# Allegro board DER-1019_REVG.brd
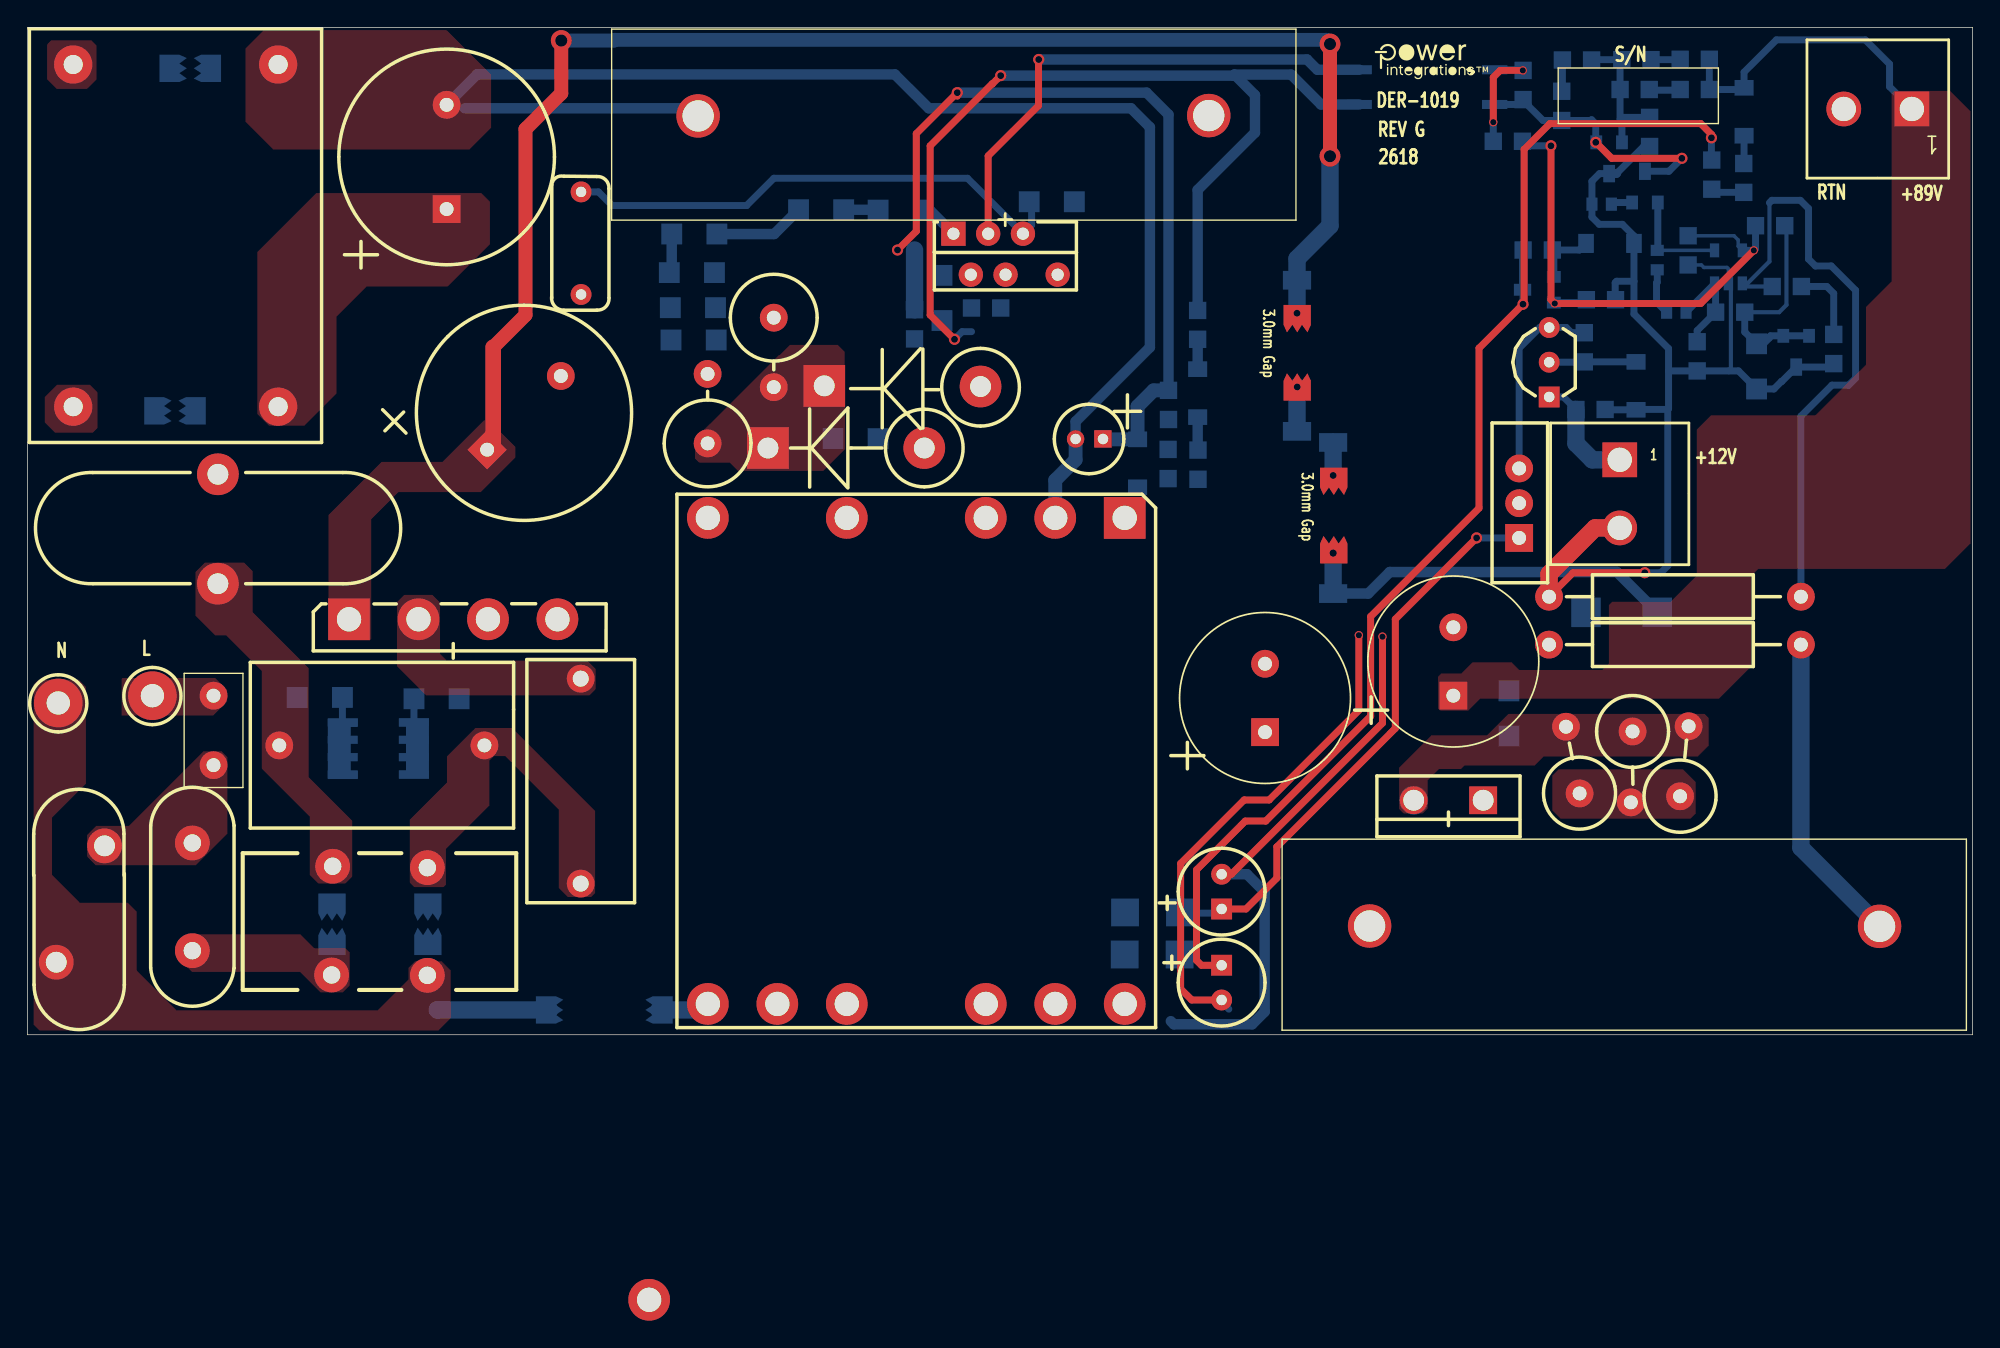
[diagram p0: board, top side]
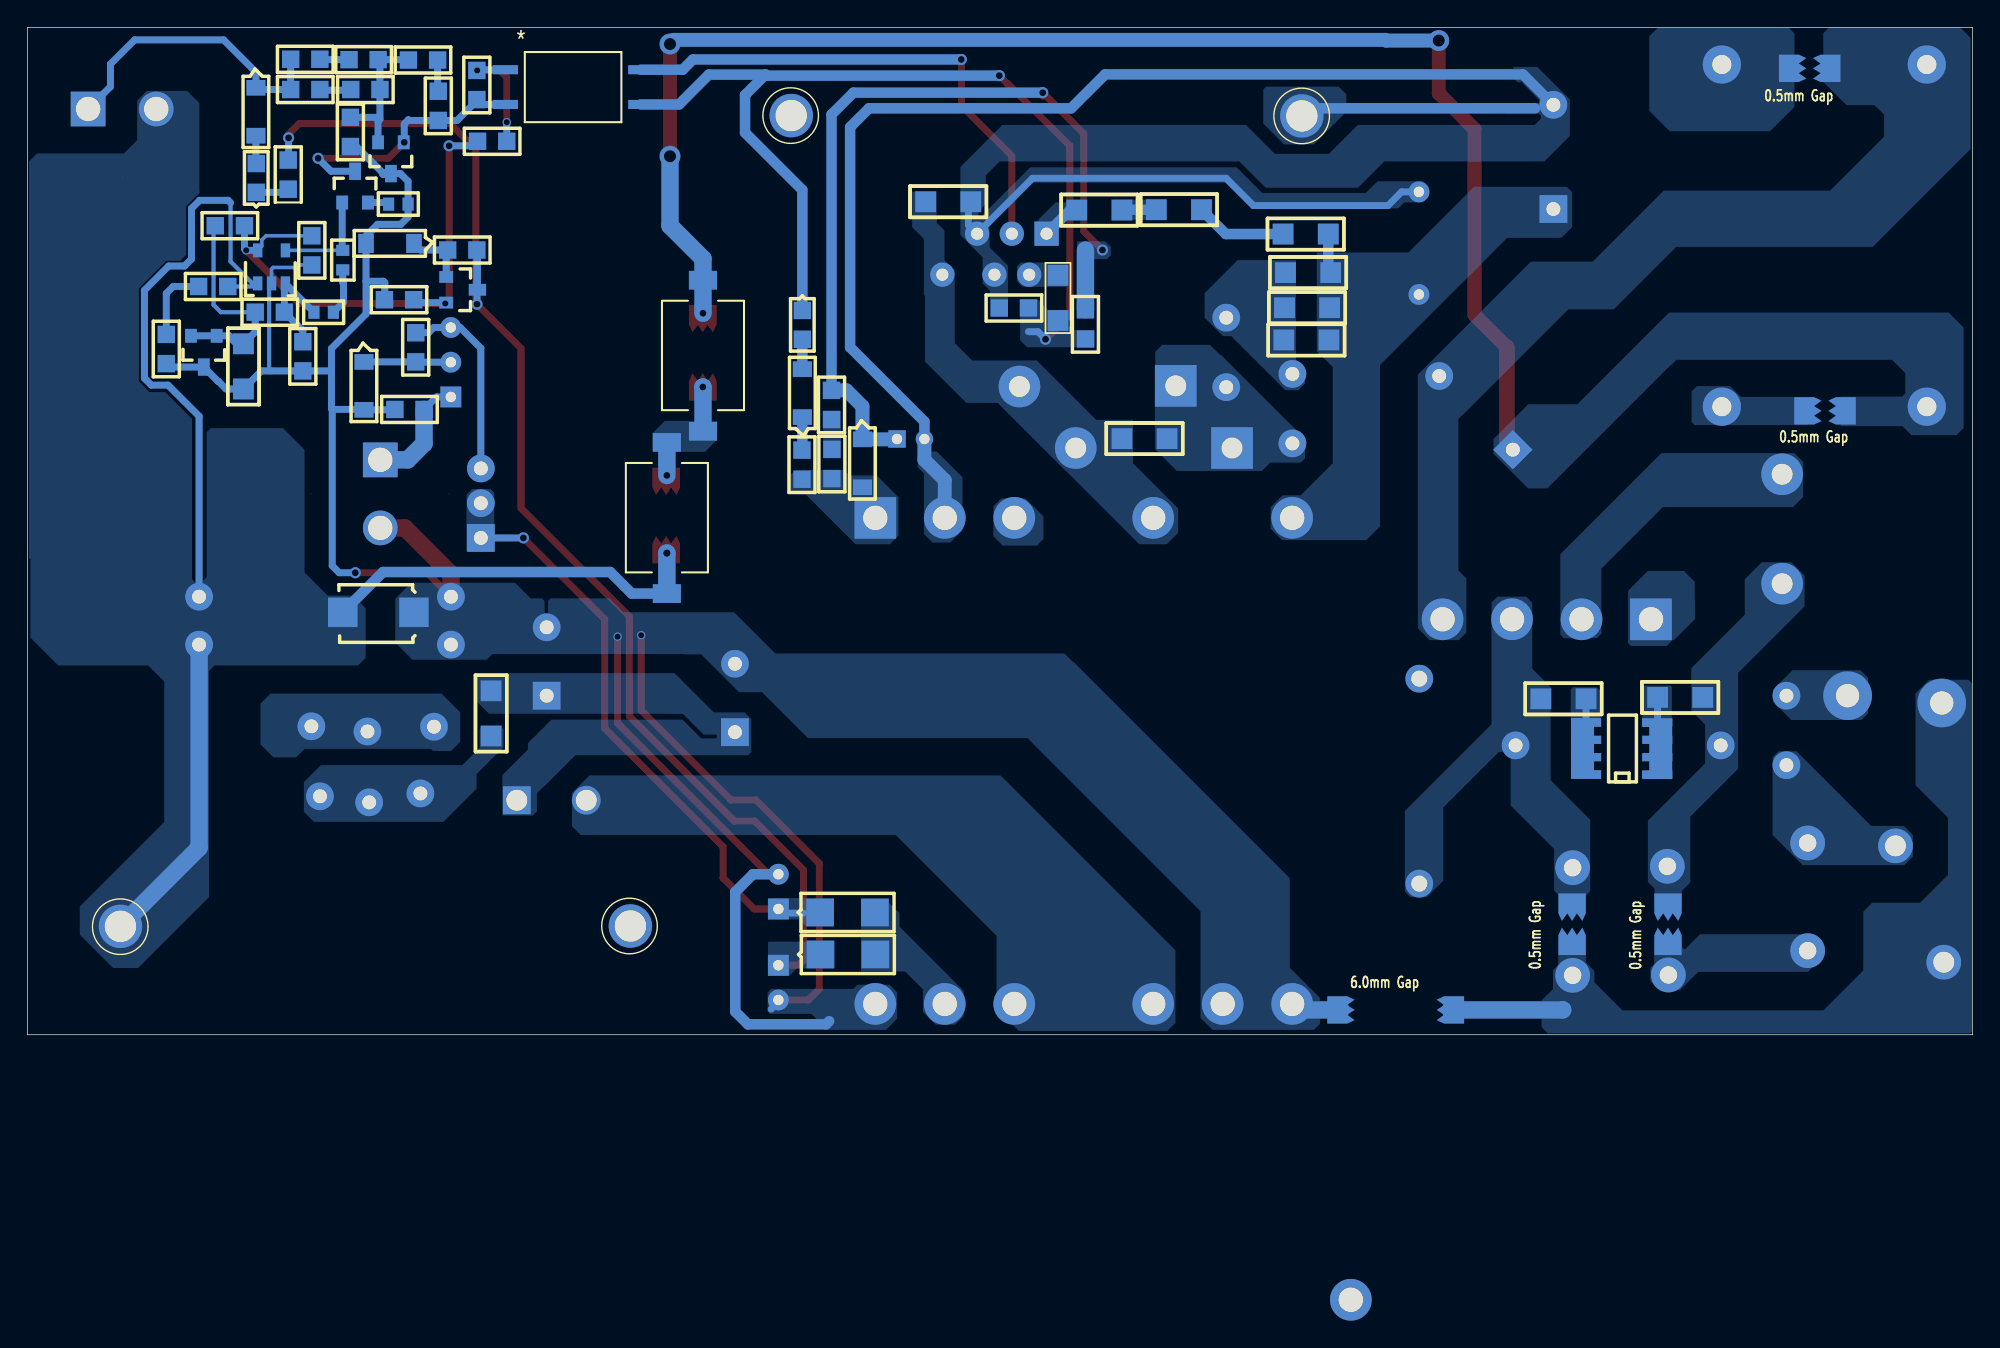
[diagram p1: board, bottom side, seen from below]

Outline 142.24 x 73.66 mm; copper layers: TOP, BOTTOM. Coordinates in mm from the lower left corner of the outline.
Outline path: 0,73.66 142.24,73.66 142.24,0 0,0 0,73.66

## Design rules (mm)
constraint set DEFAULT: min track width 0.508

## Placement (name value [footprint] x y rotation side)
BR1  GBU10KL-BP  [PIDAXBRIDGEGBU8]  23.52 30.38 0 top
C1  100 uF  [PIPOLCAPCYLD250LS100030]  87.33 9.19 90 top
C2  120 uF  [PIPOLCAPCLYD630LS300040]  33.62 42.78 45 top
C3  120 uF  [PIPOLCAPCLYD630LS300040]  30.66 60.38 90 top
C4  100 pF  [PISMC1206]  73.25 60.91 0 bottom
C5  4.7 uF  [PISMC0805]  69.04 53.14 0 bottom
C6  10 nF  [PISMC1206]  47.07 50.8 0 bottom
C7  47 pF  [PISMC1206]  58.9 43.59 0 bottom
C8  330 pF  [PISMC0805]  83.41 40.67 90 bottom
C9  22 uF  [PIPOLCAPCLYD5MMD030]  77.65 43.56 180 top
C10  100 nF  [PISMC1206]  126.44 50.52 270 bottom
C11  470 pF  [PISMC1206]  108.33 21.84 90 bottom
C12  47 uF  [PIPOLCAPCYLD250LS100030]  87.33 5.08 270 top
C13  100 nF  [PISMC0805]  113.23 45.72 0 bottom
C14  10 nF  [PISMC0805]  129.72 54.71 180 bottom
C16  220 uF  [PIPOLCAPCLYD500LS200040]  90.5 22.12 90 top
C18  220 uF  [PIPOLCAPCLYD500LS200040]  104.27 24.79 90 top
C19  100 nF  [PISMC0805]  112.19 66.85 90 bottom
C21  68 nF  [PISMC0805]  118.59 69.11 180 bottom
C33  680 nF  [PINPXCAPRAD710X430720040]  33.42 21.16 180 top
C34  220 nF  [PISMC0603]  121.28 52.83 180 bottom
C40  100 nF  [PISMC0805]  121.44 56.29 90 bottom
C41  100 nF  [PISMC0805]  114 53.75 0 bottom
C45  330 nF  [PINPXCAPRAD710X315590046]  40.46 26.04 270 top
C46  68 nF  [PI_NP_CAP_RAD9P8X4P2X7P5X0P6]  40.49 54.13 90 top
CY1  2.2 nF  [PISMC8X6MM]  92.84 55.17 270 bottom
CY2  2.2 nF  [PISMC8X6MM]  95.48 43.31 270 bottom
D1  1N5408G  [PIDV300X200X060DO15D0201AD]  62.08 47.4 0 top
D2  S1MLHRVG  [PI_SM_SOD-123_12]  81.18 43.54 270 bottom
D3  US1D  [PISMDSMA]  84.25 5.87 180 bottom
D4  STTH12R06D  [PIDVT0220ACREVA]  106.45 17.14 180 top
D7  S1AB-13-F  [PISMSMB]  113.97 30.89 0 bottom
D10  1N4148WS  [PISMDSOD323]  85.57 52.96 270 bottom
D11  US1D  [PISMDSMA]  84.28 8.94 180 bottom
D13  1N4148WS  [PISMDSOD323]  125.5 61.59 90 bottom
D14  1N5408G  [PIDV300X200X060DO15D0201AD#2]  54.15 42.9 0 top
F1  10 A  [PI_MST_MICROFUSE]  13.61 22.25 270 top
J2  FAN  [PI_HDR_2PIN_PHOENIX_196LS]  116.43 42.04 270 top
J4  FAN  [PI_HDR_2PIN_PHOENIX_196LS]  137.79 67.69 180 top
L1  100 uH  [PI2P455X1062LS315D60]  13.93 32.98 90 top
L2  1.1 mH  [PI_IND_4P_10X20MMD050]  22.15 3.28 90 top
L3  10 mH  [PIIND4P1180X827LS985590D055]  3.35 70.94 0 top
L4  48 Ohms  [PISMFERRITEBEAD1206]  66.88 55.52 270 bottom
MTG_HOLE1  No 2  [PIMTGHOLE2]  98.15 7.95 0 top
MTG_HOLE2  No 2  [PIMTGHOLE2]  135.43 7.92 0 top
MTG_HOLE3  No 2  [PIMTGHOLE2]  49.05 67.18 0 top
MTG_HOLE4  No 2  [PIMTGHOLE2]  86.39 67.21 0 top
NOREF  -  []  0 0 90 top
NOREF#2  -  []  -150.78 54.23 0 top
NOREF#3  -  []  0 73.66 0 top
NOREF#4  -  []  -228.6 -144.78 0 top
NOREF#5  -  []  141.78 0.33 90 top
NOREF#6  -  []  97.97 72.34 0 top
NOREF#7  -  []  91.74 0.33 0 top
Q1  ZTX692B  [PITO92R100]  111.28 46.63 90 top
Q2  MMBTA06LT1  [PISMSOT23123_1]  110.52 54.48 270 bottom
Q3  MMBTA06LT1  [PISMSOT23123_1]  118.29 61.95 180 bottom
R1  100 k  [PISMR1206]  19.74 24.66 0 bottom
R2  100 k  [PISMR1206]  28.27 24.56 0 bottom
R5  2 M  [PISMR1206]  47.12 58.55 0 bottom
R6  3.30 M  [PISMR1206]  56.39 60.33 0 bottom
R7  2.7 M  [PISMR1206]  62.2 60.3 0 bottom
R8  20  [PI_3W_VRES220LS200D040]  54.58 52.43 270 top
R9  20  [PI_3W_VRES220LS200D040]  49.74 43.24 90 top
R10  200 k  [PISMR1206]  50.24 55.73 180 bottom
R12  2.74 k  [PISMR0805]  64.87 50.88 90 bottom
R13  200 k  [PISMR1206]  47.02 53.16 0 bottom
R14  100  [PISMR0805]  83.44 44.98 90 bottom
R15  4.22 k  [PISMR0805]  126.36 59.16 0 bottom
R16  75  [PI2WRESD200LS725D040]  117.37 22.17 270 top
R17  75  [PI2WRESD200LS725D040#2]  113.5 17.64 101.5 top
R18  3.30 k  [PISMR0805]  113.84 49.2 90 bottom
R19  53.6 k  [PISMR0805]  125.58 52.83 180 bottom
R20  1 k  [PISMR0805]  132.08 49.07 90 bottom
R21  3.9 k  [PISMR0805]  122.1 50.67 270 bottom
R23  13.3 k  [PISMR0805]  111.51 57.38 180 bottom
R24  100  [PISMR0603]  114.4 60.73 0 bottom
R25  1.00 k  [PISMR0805]  109.37 70.51 270 bottom
R26  825 R  [PISMR0805]  109.32 65.33 180 bottom
R27  0.080  [PI1WRESD200LS725D040]  111.27 32.03 0 top
R28  15 k  [PISMR0805]  112.24 71.27 0 bottom
R29  340 k  [PISMR0805]  122.99 71.32 180 bottom
R30  10 k  [PISMR0805]  118.62 67.08 270 bottom
R32  10 k  [PISMR0805]  122.99 69.11 180 bottom
R40  47.0  [PISMR0805]  85.6 40.61 90 bottom
R41  3.32 k  [PISMR0603]  119.18 55.93 90 bottom
R50  0.080  [PI1WRESD200LS725D040]  111.27 28.52 0 top
R52  100  [PISMR0805]  123.16 61.82 90 bottom
R55  7.50 k  [PISMR0805]  118.72 71.3 180 bottom
R57  75  [PI2WRESD200LS725D040]  120.85 17.43 83.6 top
RT1  1  [PI_RAD_240X630LS310D050]  12.06 6.15 90 top
RV1  275 Vac  [PIDISC675X225LS335X140040]  2.11 5.3 90 top
SG1  0.5mm gap  [PI_SPARK_GAP_0P5MM]  22.28 8.08 90 bottom
SG2  0.5mm gap  [PI_SPARK_GAP_0P5MM]  29.29 8.08 90 bottom
SG3  0.5mm gap  [PI_SPARK_GAP_0P5MM]  11.91 70.66 180 bottom
SG4  0.5mm gap  [PI_SPARK_GAP_0P5MM]  10.79 45.62 180 bottom
SG7  3.0mm gap  [PI_SPARK_GAP_3P0MM]  95.52 37.97 270 top
SG8  3.0mm gap  [PI_SPARK_GAP_3P0MM]  92.85 49.86 270 top
SG9  6.0mm gap  [PI_SPARK_GAP_6P0MM]  42.19 1.81 0 bottom
SW1  SPDT SLIDE  [PI_SWITCH_SPDT_SLIDE_PCBM_1]  109.08 36.33 0 top
T1  PQ35/35  [PI_BOBBIN_PQ35_35V_12P]  65 20.02 270 top
TP1  WHT  [PITPKEYSTONE125X125]  2.26 24.26 0 top
TP2  BLK  [PITPKEYSTONE125X125]  9.14 24.79 0 top
U1  CAP300DG  [PI_IC_SMD_SO8_CAPZERO]  23.06 19.02 90 bottom
U2  TOP7078E  [PIICESIP76TH]  67.72 58.57 0 top
U3  SFH6106-3T  [SMD-4_VO_VIS]  102.34 69.29 180 bottom
U4  LM321MF/NOPB  [PISMSOT235]  125.4 54.94 180 bottom
U5  LM431BIM3/NOPB  [PISMSOT23123]  116.6 65.25 0 bottom
U6  LM431BIM3/NOPB  [PISMSOT23123]  130.28 51.1 0 bottom
VR4  MMSZ5241B-7-F  [PI_SM_SOD-123_12]  113.97 57.86 0 bottom
VR6  MMSZ5240B-7-F  [PI_SM_SOD-123_12]  85.57 45.16 90 bottom
VR7  MMSZ4700T1G  [PI_SM_SOD-123_12]  117.63 49.2 270 bottom
VR8  MMSZ5267BT1G  [PI_SM_SOD-123_12]  125.53 69.24 270 bottom

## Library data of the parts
BR1 = DISCRETE BRIDGE_+~~-: room: 1
C1 C12 = CAP POL: alternate symbols: (pipolcapcyld250ls100030h); room: 2
C2 C3 = CAP POL: alternate symbols: (pipolcapclyd630ls3000401260h); room: 1
C4 C6 C7 = CAP NP: tolerance: 10; room: 1
C5 = CAP NP: alternate symbols: (Unisem_RMCF0805UL); room: 1
C8 = CAP NP: alternate symbols: (Unisem_RMCF0805UL); tolerance: 10; room: 1
C9 = CAP POL: alternate symbols: (pipolcapclyd5x11mmd030H); tolerance: 20; room: 1
C10 C14 = CAP NP: room: 3
C11 = CAP NP: tolerance: 10; room: 2
C13 C19 C21 C40 C41 = CAP NP: alternate symbols: (Unisem_RMCF0805UL); room: 3
C16 C18 = CAP POL: alternate symbols: (pipolcapclyd500ls2000401200lh); room: 2
C33 = CAP NP: alternate symbols: (pinpxcaprad710x430720040_h); room: 1
C34 = CAP NP: alternate symbols: (Unisem_RMCF0603UL); room: 3
C45 = CAP NP: alternate symbols: (pinpxcaprad710x315590046H)
C46 = CAP NP
CY1 CY2 = CAP NP: tolerance: 20; room: 1
D1 D14 = DIODE: alternate symbols: (pidv300x472x060do14wbead,pidax800x225060do15do201ad,pidv300x200x060do14wbead); room: 1
D2 D10 D13 = DIODE: room: 1
D3 D7 D11 = DIODE: room: 2
D4 = DIODE
F1 = FUSE: alternate symbols: (pi_MST_microfuseH)
J2 J4 = CON2: alternate symbols: (pi_hdr_2pin_phoenix_196lsobl); room: 3
L1 = INDUCTOR: room: 1
L2 = TORRID 4P_14_23
L3 = INDUCTOR_4P-12P
L4 = INDUCTOR_BEAD
MTG_HOLE1-MTG_HOLE4 = MTG_HOLE_2-56
Q1 = NPN_EBC: alternate symbols: (PIT092100)
Q2 = NPN_BEC: room: 2
Q3 = NPN_BEC: room: 3
R1 R2 R5-R7 R10 R13 = R: room: 1
R8 R9 = R: alternate symbols: (pi_3w_vres220ls300d040,pi_3w_vres220ls400d040,pi_3w_vres220ls500d040,pi_3w_hres220ls800d040); room: 1
R12 R14 R40 = R: alternate symbols: (Unisem_RMCF0805UL); room: 1
R15 R18 R19 R21 R28-R30 R32 R55 = R: alternate symbols: (Unisem_RMCF0805UL); room: 3
R16 R17 R57 = R: alternate symbols: (pi2wresd200ls900d040,pi2wvresd200ls300d040,pi2wvresd200ls400d040); room: 2
R20 = R: room: 3
R23 R25 R26 R52 = R: alternate symbols: (Unisem_RMCF0805UL); room: 2
R24 R41 = R: alternate symbols: (Unisem_RMCF0603UL); room: 3
R27 R50 = R: alternate symbols: (pi1wvresd200ls300d040); room: 2
RT1 = THERMISTOR
RV1 = VARISTOR: room: 1
SG1-SG4 SG7 SG8 = SPARK_GAP: room: 1
SG9 = SPARK_GAP
SW1 = SW SLIDE-SPDT
T1 = BPQ35/35_12P/GENERIC: room: 1
TP1 TP2 = TESTPOINT: alternate symbols: (TP_5010-14)
U1 = CAPZero: room: 1
U2 = TOPSwitch-GaN_eSIP7
U3 = OPTO_A_B_AKCE: User Part Number: PN; Tolerance: TOL
U4 = LM321_SOT23-5
U5 U6 = TL431/SOT-23_CAR: room: 3
VR4 VR6-VR8 = DIODE_ZENER: room: 2

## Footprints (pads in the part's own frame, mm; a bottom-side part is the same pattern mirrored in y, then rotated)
PI1WRESD200LS725D040
  round 2.032 hole 1.016: 1(0,0) 2(18.415,0)
PI2P455X1062LS315D60
  round 3.048 hole 1.524: 1(0,0) 2(8.001,0)
PI2WRESD200LS725D040
  round 2.032 hole 1.016: 1(0,0) 2(5.156,-0.051)
PI2WRESD200LS725D040#2
  round 2.032 hole 1.016: 1(0,0) 2(4.978,0)
PI_3W_VRES220LS200D040
  round 2.032 hole 1.016: 1(0,0) 2(5.08,0)
PI_BOBBIN_PQ35_35V_12P
  rect 3.048x3.048 hole 1.778: 1(-17.77,15.24)
  round 3.048 hole 1.778: 2(-17.77,10.16) 3(-17.77,5.08) 4(-17.77,-5.08) 5(39.406,-19.533) 6(-17.77,-15.24) 7(17.77,-15.24) 8(17.77,-10.16) 9(17.77,-5.08) 10(17.77,5.08) 11(17.77,10.16) 12(17.77,15.24)
PI_HDR_2PIN_PHOENIX_196LS
  rect 2.54x2.54 hole 1.778: 1(0,0)
  round 2.54 hole 1.778: 2(4.978,0)
PI_IC_SMD_SO8_CAPZERO
  rect 0.599x2.2 smd: 1(0,0) 2(1.27,0) 3(2.54,0) 4(3.81,0) 5(3.81,5.199) 6(2.54,5.199) 7(1.27,5.199) 8(0,5.199)
PI_IND_4P_10X20MMD050
  round 2.54 hole 1.27: 1(1.092,-0.099) 2(1.067,-7.099) 3(8.938,-7.099) 4(9.04,-0.175)
PI_MST_MICROFUSE
  round 2.032 hole 1.016: 1(-2.54,0) 2(2.54,0)
PI_NP_CAP_RAD9P8X4P2X7P5X0P6
  round 1.524 hole 0.762: 1(0,0) 2(7.501,0)
PI_RAD_240X630LS310D050
  round 2.54 hole 1.27: 1(0,0) 2(7.874,0)
PI_SM_SOD-123_12
  rect 1.143x1.397 smd: 1(0,0) 2(3.505,0)
PI_SPARK_GAP_0P5MM
  custom 0.5x0.5 smd: 1(-1.25,0) 2(1.25,0)
PI_SPARK_GAP_3P0MM
  custom 0.5x0.5 smd: 1(-2.499,0) 2(2.499,0)
PI_SPARK_GAP_6P0MM
  custom 0.5x0.5 smd: 1(-4,0) 2(4,0)
PI_SWITCH_SPDT_SLIDE_PCBM_1
  rect 2.032x2.032 hole 1.016: 1(0,0)
  round 2.032 hole 1.016: 2(0,2.54) 3(0,5.08)
PIDAXBRIDGEGBU8
  rect 3.048x3.048 hole 1.778: 1(0,0)
  round 3.048 hole 1.778: 2(5.08,0) 3(10.16,0) 4(15.24,0)
PIDISC675X225LS335X140040
  round 2.54 hole 1.524: 1(0,0) 2(8.509,-3.531)
PIDV300X200X060DO15D0201AD
  rect 3.048x3.048 hole 1.524: 1(-3.81,0.051)
  round 3.048 hole 1.524: 2(7.62,0)
PIDV300X200X060DO15D0201AD#2
  rect 3.048x3.048 hole 1.524: 1(0,0)
  round 3.048 hole 1.524: 2(11.43,0)
PIDVT0220ACREVA
  rect 2.032x2.032 hole 1.524: 1(0,0)
  round 2.032 hole 1.524: 2(5.08,0)
PIICESIP76TH
  rect 1.778x1.778 hole 0.889: 1(0,0)
  round 1.778 hole 0.889: 2(1.27,-2.997) 3(2.54,0) 4(3.81,-2.997) 5(5.08,0) 7(7.62,-2.997)
PIIND4P1180X827LS985590D055
  round 2.794 hole 1.397: 1(0,0) 6(0,-25.019) 7(14.986,-25.019) 12(14.986,0)
PIMTGHOLE2
  round 3.175 hole 2.286: 1(0,0)
PINPXCAPRAD710X315590046
  round 2.032 hole 1.168: 1(0,0) 2(14.986,0)
PINPXCAPRAD710X430720040
  round 2.032 hole 1.016: 1(0,0) 2(15.001,0)
PIPOLCAPCLYD5MMD030
  rect 1.27x1.27 hole 0.762: 1(-1.001,0)
  round 1.27 hole 0.762: 2(1.001,0)
PIPOLCAPCLYD500LS200040
  rect 2.032x2.032 hole 1.016: 1(0,0)
  round 2.032 hole 1.016: 2(5.001,0)
PIPOLCAPCLYD630LS300040
  rect 2.032x2.032 hole 1.016: 1(0,0)
  round 2.032 hole 1.016: 2(7.62,0)
PIPOLCAPCYLD250LS100030
  rect 1.524x1.524 hole 0.762: 1(0,0)
  round 1.524 hole 0.762: 2(2.54,0)
PISMC8X6MM
  rect 1.369x2.06 smd: 1(0,0) 2(11.049,0)
PISMC0603
  rect 0.813x0.965 smd: 1(0,0) 2(1.422,0)
PISMC0805
  rect 1.27x1.27 smd: 1(0,0) 2(2.134,0)
PISMC1206
  rect 1.524x1.524 smd: 1(0,0) 2(3.302,0)
PISMDSMA
  rect 2.032x2.032 smd: 1(0,0) 2(4.013,0)
PISMDSOD323
  rect 1.27x1.27 smd: 1(0,0) 2(2.108,0)
PISMFERRITEBEAD1206
  rect 1.524x1.524 smd: 1(0,0) 2(3.302,0)
PISMR0603
  rect 0.813x0.965 smd: 1(0,0) 2(1.422,0)
PISMR0805
  rect 1.27x1.27 smd: 1(0,0) 2(2.134,0)
PISMR1206
  rect 1.524x1.524 smd: 1(0,0) 2(3.302,0)
PISMSMB
  rect 2.159x2.159 smd: 1(0,0) 2(5.207,0)
PISMSOT235
  rect 0.686x1.016 smd: 1(0,0) 2(1.016,0) 3(2.032,0) 4(2.032,2.413) 5(0,2.413)
PISMSOT23123
  rect 0.864x1.016 smd: 1(-1.88,0) 3(0,0)
  rect 0.864x1.27 smd: 2(-0.94,2.286)
PISMSOT23123_1
  rect 0.864x1.016 smd: 1(-0.93,-1.1) 2(0.95,-1.1)
  rect 0.864x1.27 smd: 3(0.01,1.186)
PITO92R100
  rect 1.524x1.524 hole 0.762: 1(0,0)
  round 1.524 hole 0.762: 2(2.54,0) 3(5.08,0)
PITPKEYSTONE125X125
  round 3.556 hole 1.702: 1(0,0)
SMD-4_VO_VIS
  rect 1.854x0.66 smd: 1(-4.953,1.27) 2(-4.953,-1.27) 3(4.953,-1.27) 4(4.953,1.27)

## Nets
SGND: C1.2 C10.2 C12.2 C13.2 C16.2 C18.2 C40.1 C41.2 D7.1 J2.2 R20.1 R21.2 R24.1 R27.1 R30.2 R50.1 SG9.2 T1.7 T1.8 T1.12 U4.2(V-) U5.2 U6.2 VR4.2 VR7.2
ISENSE: C14.2 CY2.2 D7.2 J4.2 MTG_HOLE2.1 R27.2 R50.2 SG7.2 U4.1
SOURCE: C3.2 C4.1 C5.2 C9.2 C46.2 L3.12 MTG_HOLE3.1 SG3.1 T1.2 U2.4 U2.5
VOUT: C11.2 C16.1 C18.1 D4.1 J4.1 R29.1 R32.1 VR8.1
N1180656: C3.1 C6.1 C46.1 L3.7 R5.1 R10.2 R13.1 SG4.1 T1.6
N1180866: BR1.1 C2.1 CY1.1 L3.6 SG4.2 SG8.1
N1181140: BR1.4 C2.2 L3.1 SG3.2
N1181144: R5.2 R6.1
N1181148: C4.2 C7.2 D1.2 D14.2 T1.4 U2.7
N1181266: C9.1 D2.1 R12.2 R14.2
N11509809: L2.2 RV1.1 SG2.1 SG9.1 TP1.1
N11618494: C8.1 D2.2 R40.1 T1.1
N11648004: R6.2 R7.1
N12700328: R7.2 U2.1
N12700744: C5.1 D10.1 L4.2 R12.1 U3.3
N12706416: C11.1 R16.2 R17.1 R57.1
N12706737: D4.2 R16.1 R17.2 R57.2 T1.9 T1.10
N12714802: C12.1 D3.1 Q2.3 R23.2 R52.2
N12714836: C40.2 C41.1 Q2.2(EMITTER) R15.1 R26.1 U4.5
N12714870: Q2.1 R23.1 VR4.1
N12715244: R25.1 R26.2 U3.1
N12715260: C21.1 R32.2
N12715348: C19.1 Q3.3 R25.2 U3.2 U5.1
N12715352: R29.2 R55.1
N12715398: C21.2 R28.2 R30.1 R55.2 U5.3(VREF)
N12715470: C19.2 R28.1
N12715572: C14.1 R20.2
N12715722: C10.1 R15.2 R19.1 U6.1 U6.3(VREF)
N12715816: C34.1 R19.2 R21.1 U4.3
N12715884: Q3.2(EMITTER) R24.2
N12720334: D3.2 D11.2 T1.11
N12771158: U2.3 U3.4(E)
N12827596: F1.1 TP2.1
N12850742: C6.2 R8.1 R9.2 R10.1 R13.2
N12884562: BR1.2 C45.1 L1.2
N12884633: BR1.3(AC2) C33.1 C45.2 L2.3 R2.2 SG2.2
N12888086: Q1.3 R18.2 SW1.3
N12888112: C13.1 J2.1 Q1.1(EMITTER)
N12888140: Q1.2 R18.1 VR7.1
N12889668: CY1.2 CY2.1 SG7.1 SG8.2
N12891407: L4.1 U2.2
N12908406: F1.2 RT1.2 RV1.2
N12908860: C33.2 L1.1 L2.4 R1.1 SG1.2
N12919791: C7.1 D1.1 D14.1 R8.2 R9.1
N12926277: R1.2 U1.1 U1.2 U1.3 U1.4
N12926285: R2.1 U1.5 U1.6 U1.7 U1.8(NC8)
N12928762: L2.1 RT1.1 SG1.1
N12942914: C1.1 D11.1 SW1.1 SW1.2
N12947787: D10.2 VR6.2
N12947838: R40.2 VR6.1
N12951060: C34.2 R41.1
N12953138: Q3.1 R41.2 U4.4
N13029746: C8.2 R14.1
N13057790: D13.1 R52.1
N13059217: D13.2 VR8.2

Pads without a net: MTG_HOLE1 1; MTG_HOLE4 1; T1 3 5

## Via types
v1: diameter 0.813, hole 0.508, TOP to BOTTOM, 17 vias
v2: diameter 0.61, hole 0.457, TOP to BOTTOM, 6 vias
v3: diameter 1.524, hole 0.889, TOP to BOTTOM, 3 vias

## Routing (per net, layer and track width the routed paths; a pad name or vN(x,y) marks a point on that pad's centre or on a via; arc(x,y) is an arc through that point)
SGND: length 168.8
  TOP w0.508: v1(118.26,33.78) 113.02,33.78 R27.1 ; C1.2 88.04,11.73 99.09,22.78 v2(99.09,29.11) ; v2(97.36,29.21) 97.36,23.72 90.81,17.17 88.98,17.17 84.33,12.52 84.33,3.35 85.14,2.54 C12.2
  TOP w1.27: J2.2 114.63,37.06 111.27,33.7 R27.1
  BOTTOM w0.254: C40.1 122.4,56.29 122.59,56.1 124.28,56.1 124.38,56 U4.2
  BOTTOM w0.305: U4.2 124.56,54.76 124.56,48.69 124.41,48.54
  BOTTOM w0.508: 120,48.54 120,50.18 117.47,52.7 117.47,55.09 ; 120,48.54 R21.2 125.12,48.54 C10.2 127.71,47.22 128.27,47.78 128.3,47.78 U6.2 131.83,48.82 R20.1 ; 120,48.54 120,45.78 119.95,45.73 ; C41.2 116.1,53.77 116.1,54.99 116.2,55.09 117.47,55.09 ; v1(118.26,33.78) 119.44,33.78 119.95,34.29 119.95,45.73 ; 117.47,55.09 VR4.2 117.47,58.41 116.63,59.26 114.94,59.26 114.4,59.79 R24.1 114.4,62.41 114.96,62.97 U5.2 ; 49.22,1.81 49.27,1.76 49.32,1.81 ; 119.95,45.73 117.66,45.73 VR7.2 115.39,45.69 C13.2 ; 87.85,1.87 87.33,2.4 C12.2 ; R30.2 118.18,64.95 116.23,63
  BOTTOM w0.635: 116.23,63 116.2,62.97 U5.2
  BOTTOM w0.762: C1.2 89.18,11.73 90.47,10.44 90.47,1.68 89.55,0.76 83.84,0.76 83.61,0.99
  BOTTOM w1.27: SG9.2 49.32,1.81 T1.7
ISENSE: length 96.8
  BOTTOM w0.305: C14.2 125.63,54.71 U4.1 125.78,54.94 127.38,56.54 127.38,60.83
  BOTTOM w0.508: 127.38,60.83 127.56,61.01 129.64,61.01 130.24,60.41 130.24,56.72 130.75,56.21 131.9,56.21 133.68,54.43 133.68,48.01 133.17,47.5 131.95,47.5 129.68,45.23 R27.2
  BOTTOM w0.762: CY2.2 98.04,32.26 99.62,33.83 116.23,33.83 D7.2
  BOTTOM w1.27: MTG_HOLE2.1 129.68,13.68 R50.2 ; CY2.2 v1(95.48,35.2) v1(95.48,35.23)
SOURCE: length 140.6
  BOTTOM w0.508: C4.1 73.43,60.73 73.43,59.21 U2.5 68.75,62.62 54.58,62.62 52.59,60.63 42.76,60.63 41.76,61.63 C46.2
  BOTTOM w0.762: C3.2 32.88,70.22 63.44,70.22 65.91,67.74 80.7,67.74 82.08,66.36 82.08,50.26 76.65,44.83 C9.2 ; MTG_HOLE3.1 48.49,67.74 31.99,67.74
  BOTTOM w1.016: T1.2 75.16,40.55 76.65,42.04 C9.2
VOUT: length 22.3
  BOTTOM w0.508: R29.1 R32.1 125.4,69.11 VR8.1 125.53,70.38 127.89,72.75 134.39,72.75 136.16,70.97 136.16,69.32 J4.1
N1180656: length 2.9
  BOTTOM w0.762: R5.1 47.12,55.91 R10.2
N1180866: length 109.4
  TOP w1.016: 34.06,50.27 36.42,52.63 36.42,66.22 39.04,68.83 v3(39.04,72.69) ; v3(95.25,64.24) v3(95.25,72.44)
  TOP w1.143: 33.86,42.51 34.06,42.71 34.06,50.27
  BOTTOM w1.016: v3(95.25,72.44) 94.95,72.75 42.95,72.75 42.9,72.69 v3(39.04,72.69)
  BOTTOM w1.27: v3(95.25,64.24) 95.25,59.16 92.84,56.74 CY1.1 v1(92.84,52.76)
N1181144: length 6.7
  BOTTOM w0.762: R5.2 54.61,58.55 R6.1
N1181266: length 61.9
  TOP w0.508: v1(63.63,57.38) 65,58.75 65,65.89 v1(68,68.88) 68,68.63
  BOTTOM w0.762: 83.44,47.12 83.44,67.28 81.84,68.88 v1(68,68.88)
  BOTTOM w1.016: 83.44,47.12 82.35,47.12 81.18,45.95 D2.1 78.67,43.54 C9.1
  BOTTOM w1.27: R12.2 64.87,57.38
N11509809: length 8.2
  BOTTOM w1.27: 29.97,1.83 29.99,1.81 SG9.1
N11648004: length 2.5
  BOTTOM w0.762: R6.2 62.18,60.33 R7.1
N12700328: length 2.9
  BOTTOM w0.762: U2.1 65.99,60.3 R7.2
N12700744: length 70.4
  TOP w0.508: v1(71.17,70.13) 70.58,69.54 70.55,69.54 66.01,65 66.01,52.63 v1(67.79,50.85)
  BOTTOM w0.508: 69.04,51.41 68.35,51.41 v1(67.79,50.85)
  BOTTOM w0.762: 88.27,70.21 89.76,68.71 89.76,65.96 85.57,61.77 D10.1 ; 88.27,70.21 88.19,70.13 v1(71.17,70.13) ; 88.27,70.21 92.41,70.21 94.59,68.02 U3.3
N12714802: length 95.7
  TOP w0.508: v1(123.14,65.58) 123.14,65.84 122.35,66.62 111.33,66.62 109.44,64.74 109.44,53.49 v1(109.36,53.42) 106.15,50.2 106.15,38.51 98.22,30.58 98.22,23.29 90.55,15.62 89.05,15.62 85.49,12.06 85.49,5.44 85.85,5.08 C12.1
  BOTTOM w0.508: Q2.3 109.33,57.34 R23.2 109.37,54.26 109.36,54.25 v1(109.36,53.42) ; R52.2 123.14,63.98 v1(123.14,65.58)
N12714836: length 39.9
  TOP w0.508: v2(126.24,57.35) 122.35,53.47 v2(111.68,53.47) 111.4,53.75 v1(111.4,65)
  BOTTOM w0.254: U4.5 125.09,57.66 125.09,58.12 124.79,58.42 C40.2
  BOTTOM w0.508: U4.5 v2(126.24,57.35) 126.36,57.48 R15.1 ; C41.1 113.78,53.53 Q2.2 ; R26.1 109.65,65 v1(111.4,65) 111.46,64.95
N12714870: length 4.7
  BOTTOM w0.508: Q2.1 111.62,57.27 R23.1 113.49,57.38 VR4.1
N12715244: length 9.1
  TOP w0.508: v2(107.19,66.73) 107.19,70 107.7,70.51 v2(109.35,70.51)
  BOTTOM w0.508: R25.1 v2(109.35,70.51) 109.3,70.56 U3.1 ; v2(107.19,66.73) R26.2
N12715260: length 2.3
  BOTTOM w0.508: R32.2 120.8,69.06 118.64,69.06 C21.1
N12715348: length 19.7
  TOP w0.508: v1(114.68,65.25) 115.85,64.08 v1(120.98,64.08)
  BOTTOM w0.508: Q3.3 120.03,63.14 v1(120.98,64.08) 121.01,64.08 121.03,64.06 ; U5.1 v1(114.68,65.25) 114.68,66.6 114.38,66.9 114.33,66.85 C19.1 110.82,66.85 109.68,68 109.68,68.05 109.37,68.35 R25.2 109.35,68.38 108.99,68.02 U3.2
N12715352: length 2.1
  BOTTOM w0.508: R55.1 120.83,71.3 R29.2
N12715398: length 10.6
  BOTTOM w0.508: U5.3 116.6,66.81 116.51,66.9 ; R28.2 114.4,71.3 R55.2 116.46,71.17 C21.2 116.46,66.95 116.51,66.9 ; 116.51,66.9 116.69,67.08 R30.1
N12715470: length 2.3
  BOTTOM w0.508: C19.2 112.24,69.04 R28.1
N12715572: length 5.6
  BOTTOM w0.508: R20.2 132.08,54.2 131.57,54.71 C14.1
N12715722: length 16
  BOTTOM w0.305: R19.1 128.09,52.83 128.63,53.37 128.63,59.03 R15.2
  BOTTOM w0.508: R19.1 125.58,51.38 C10.1 126.52,50.44 126.87,50.44 127.38,50.95 127.38,51.03 127.46,51.1 U6.1 U6.3
N12715816: length 7.8
  BOTTOM w0.508: R21.1 122.1,51.49 R19.2 123.44,54.86 U4.3 123.37,54.91 C34.1
N12715884: length 1.6
  BOTTOM w0.508: Q3.2 115.94,60.85 R24.2
N12771158: length 38
  TOP w0.508: U2.3 70.26,64.26 73.94,67.94 73.94,71.3 v1(73.95,71.31)
  BOTTOM w0.762: v1(73.95,71.31) 93.57,71.31 94.32,70.56 U3.4
N12888086: length 14.3
  BOTTOM w0.508: R18.2 112.9,51.33 112.52,51.71 Q1.3 110.59,51.71 109.08,50.2 SW1.3
N12888112: length 8.5
  BOTTOM w0.508: C13.1 112.32,46.63 Q1.1
  BOTTOM w1.27: J2.1 114.43,42.04 113.23,43.23 C13.1
N12888140: length 6.4
  BOTTOM w0.508: VR7.1 R18.1 113.82,49.17 Q1.2
N12889668: length 8.9
  BOTTOM w0.508: CY1.2 92.85,44.14 v1(92.85,47.36)
  BOTTOM w1.27: CY1.2 92.84,47.35 v1(92.85,47.36) ; CY2.1 v1(95.48,40.89)
N12926277: length 1.8
  BOTTOM w0.508: U1.4 23.04,22.86 R1.2
N12926285: length 1.7
  BOTTOM w0.508: U1.5 28.27,22.84 R2.1
N12942914: length 41
  TOP w0.508: C1.1 89.1,9.19 91.36,11.46 91.36,13.74 100.03,22.4 100.03,30.38 v1(105.97,36.33)
  BOTTOM w0.508: 85.5,8.89 87.02,8.89 C1.1 ; v1(105.97,36.33) SW1.1
N12947787: length 2.2
  BOTTOM w0.762: D10.2 VR6.2
N12947838: length 2.4
  BOTTOM w0.762: R40.2 85.57,42.77 VR6.1
N12951060: length 3.4
  BOTTOM w0.508: C34.2 119.13,53.57 119.13,54.97 119.18,55.02 R41.1
N12953138: length 7.7
  BOTTOM w0.254: R41.2 U4.4
  BOTTOM w0.508: Q3.1 119.22,57.39 R41.2
N13057790: length 2.4
  BOTTOM w0.508: D13.1 123.39,61.59 R52.1
N13059217: length 2
  BOTTOM w0.508: VR8.2 125.53,63.73 D13.2

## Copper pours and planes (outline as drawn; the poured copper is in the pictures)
SGND on BOTTOM: 87.83,3.35 81.84,3.35 81.53,3.66 79.2,3.66 78.64,3.1 78.64,1.17 79.45,0.36 83.74,0.36 84.91,1.52 87.93,1.52 88.11,1.7 88.11,3.07
SGND on BOTTOM: 115.34,31.88 115.34,28.68 114.08,27.42 108.65,27.42 108.23,27.84 94.28,27.84 94.26,27.81 92.96,27.81 90.2,25.04 88.52,25.04 85.17,21.69 69.11,21.69 56.46,9.04 56.46,1.24 55.58,0.36 48.16,0.36 47.73,0.79 47.73,2.69 49.94,4.9 49.94,11.46 65.76,27.28 65.81,27.28 66.41,27.88 87.55,27.88 90.57,30.89 98.66,30.89 99.67,31.9 103.99,31.9 104.17,31.72 104.17,30.89 104.24,30.81 104.34,30.81 104.42,30.89 104.42,31.72 104.6,31.9 105.44,31.9 106.58,33.05 114.17,33.05
ISENSE on BOTTOM: 130.56,69.01 133.5,69.01 134.21,68.3 134.21,65.41 135.18,64.44 141.53,64.44 142.11,63.86 142.11,34.8 142.01,34.8 142.01,29.03 139.98,27 133.4,27 132.23,25.83 132.23,15.54 138.4,9.37 138.4,7.32 135.97,4.88 134.14,4.88 128.96,10.06 128.96,26.59 128.55,27 118.06,27 117.5,27.56 117.5,31.19 118.41,32.11 120.27,32.11 121.97,33.81 121.97,42.77 123.55,44.35 128.83,44.35 129.13,44.04 129.13,33.45 129.46,33.12 130.02,33.12 130.2,33.3 130.2,45.03 132.16,46.99 133.3,46.99 134.09,47.78 134.09,54.58 132.08,56.59 131.06,56.59 130.63,57.02 130.63,60.58 129.64,61.57 129.64,61.67 129.67,61.7 129.67,68.12
Net_24 on BOTTOM: 69.27,39.22 71.02,39.22 71.6,38.63 71.6,36.45 70.92,35.76 68.43,35.76 67.94,36.25 67.94,37.9
SOURCE on TOP: 17.3,73.46 30.66,73.46 33.91,70.21 33.91,66.32 32.32,64.73 17.97,64.73 15.95,66.75 15.95,72.11
SOURCE on BOTTOM: 72.39,54.94 71.86,54.41 71.86,52.53 70.54,52.53 70.54,56.24 71.88,57.58 71.88,59.03 72.16,59.31 72.16,59.33 72.36,59.33 72.69,59.66 72.69,60.2 72.16,60.73 72.16,62.84 71.15,63.86 53.62,63.86 51.7,61.94 44.95,61.94 43.03,63.86 31.32,63.86 29.45,65.72 29.45,68.39 31.83,70.76 33.58,70.76 33.58,69.95 33.27,69.65 33.02,69.65 32.92,69.75 32.92,69.57 31.7,68.35 31.7,68.17 31.75,68.12 34.06,68.12 34.06,67.34 31.7,67.34 31.57,67.21 31.57,66.98 32.03,66.52 44.96,66.52 47.07,64.41 51.03,64.41 53.14,66.52 70.94,66.52 74.02,63.45 74.02,58.47 72.39,56.85
SOURCE on BOTTOM: 51.87,66.62 50.34,65.1 48.18,65.1 45.8,67.49 45.8,68.76 46.37,69.33 51.65,69.33 51.87,69.11
SOURCE on BOTTOM: 73.86,36.88 74.75,35.99 76.05,35.99 76.68,36.63 76.68,41.05 77.14,41.5 77.14,41.76 76.25,42.65 75.74,42.65 73.86,40.77
SOURCE on BOTTOM: 13.03,67.84 13.03,73.2 13.46,73.63 23.01,73.63 23.65,73 23.65,67.56 22.15,66.07 14.81,66.07
SOURCE on BOTTOM: 40.18,62.41 43.51,62.41 44.37,61.54 51.94,61.54 53.82,63.42 68.91,63.42 72.85,59.49 72.85,59.16 72.72,59.03 71.98,59.03 68.71,62.31 54.56,62.31 52.68,60.43 41.99,60.43 41.55,60.86 40.18,60.86 39.78,61.26 39.78,62
VOUT on TOP: 105.36,23.7 103.3,23.7 103.15,23.85 103.15,26.19 103.38,26.42 104.85,26.42 105.66,27.23 108.53,27.23 109.09,26.67 115.16,26.67 115.65,27.15 115.65,31.42 115.89,31.66 120.15,31.66 122.07,33.58 122.07,44.25 123.11,45.29 130.73,45.29 134.44,49 134.44,53.21 136.32,55.09 136.32,68.83 136.5,69.01 140.59,69.01 142.09,67.51 142.09,35.89 142.04,35.89 140.21,34.06 126.57,34.06 126.11,33.6 126.11,27 123.67,24.56 106.22,24.56
VOUT on BOTTOM: 92.05,23.57 94.92,26.44 109.35,26.44 109.5,26.29 109.5,24.49 108.48,23.47 95.2,23.47 95.19,23.46 94.3,23.46 92.79,21.95 91.87,21.95 91.82,21.89 91.82,21.74 91.9,21.67 92.96,21.67 94.34,23.04 103.91,23.04 105.64,21.31 105.64,20.85 107.51,18.99 107.51,16.03 105.28,16.03 104.98,16.33 104.98,17.65 104.52,18.11 104.5,18.11 102.17,20.43 89.55,20.43 89.31,20.68 89.31,23.09 89.79,23.57
N1180656 on TOP: 33.2,61.54 33.82,60.92 33.82,57.8 30.73,54.71 24.82,54.71 22.61,52.5 22.61,46.89 20.24,44.53 17.68,44.53 16.81,45.39 16.81,57.23 21.13,61.54
N1180656 on BOTTOM: 12.12,44.58 11.99,44.7 11.99,46.66 12.01,46.63 16.94,46.63 17.73,47.42 20.17,47.42 20.55,47.04 20.55,44.81 20.32,44.58
N1180656 on BOTTOM: 36.45,62 41.25,57.2 47.96,57.2 47.96,49.99 46.79,48.82 46.79,41.78 49.12,39.45 50.47,39.45 51.33,38.58 51.33,37.01 50.5,36.17 44.32,36.17 43.33,37.16 43.33,48.97 34.04,58.27 30.07,58.27 29.29,59.05 29.29,61.62 29.67,62
N1180866 on TOP: 22.01,37.99 25.91,41.88 30.35,41.88 33.4,44.93 33.73,44.93 35.69,42.98 35.69,42.21 33.15,39.67 27.13,39.67 25.15,37.69 25.15,28.93 25.07,28.85 22.02,28.85 22.02,37.97
N1180866 on TOP: 2.16,47.52 4.57,47.52 5.13,46.96 5.13,44.37 4.78,44.02 2.03,44.02 1.27,44.78 1.27,46.63
N1180866 on BOTTOM: 5.13,44.5 4.47,43.84 1.19,43.84 0.66,44.37 0.66,51.71 1.75,52.81 22.2,52.81 28.91,46.1 32.49,46.1 35.04,43.55 35.04,42.48 32.51,39.95 31.09,39.95 22.11,48.93 22.07,48.93 21.65,49.35 5.89,49.35 4.93,48.39 4.93,46.89 5.16,46.66 9.65,46.66 9.65,44.53 9.63,44.5
N1180866 on BOTTOM: 21.95,28.85 21.84,28.85 20.29,30.4 20.29,31.75 20.32,31.78 20.32,33.12 21.11,33.91 23.75,33.91 25.2,32.46 25.2,28.65 24.97,28.42 22.38,28.42
N1181140 on TOP: 1.73,72.72 4.67,72.72 5.05,72.34 5.05,69.85 4.37,69.16 2.13,69.16 1.45,69.85 1.45,72.42 1.73,72.69
N1181140 on BOTTOM: 10.92,69.67 9.22,67.97 7.16,67.97 6.48,67.28 6.48,65.66 10.41,61.72 22.58,61.72 27.77,56.53 32.3,56.53 40.56,48.26 40.56,29.72 39.7,28.85 37.57,28.85 37.02,29.4 37.02,33.36 37.6,33.95 37.6,45.02 37.17,45.45 37.16,45.44 29.56,53.04 26.25,53.04 23.57,55.72 21.68,57.61 7.3,57.61 0.15,64.76 0.15,72.9 0.91,73.66 10.49,73.66 10.92,73.23
N1181148 on BOTTOM: 76.61,54.03 76.68,54.1 76.68,58.19 77.55,59.05 77.55,61.65 75.74,61.65 75.74,59.36 75.18,58.8 75.18,56.65 74.43,55.91 74.43,50.58 73.15,49.3 68.43,49.3 64.08,44.96 61.39,44.96 61.39,41.78 58.09,38.48 58.09,36.7 58.93,35.86 60.93,35.86 66.27,41.2 66.29,41.2 71.3,46.2 73.58,46.2 76.61,49.23
N1181266 on BOTTOM: 65.43,58.01 63.42,58.01 63.02,57.61 63.02,57 63.3,56.72 65.48,56.72 65.48,57.96
N11509809 on TOP: 0.81,25.96 3.76,25.96 4.28,25.44 4.28,18.35 1.8,15.88 1.8,11.68 3.84,9.65 7.34,9.65 8,8.99 8,4.7 10.92,1.78 25.6,1.78 27.86,4.04 27.86,4.88 28.36,5.37 30.29,5.37 30.96,4.7 30.96,1.22 30.07,0.33 30.07,0.3 0.89,0.3 0.46,0.74 0.46,25.6
N11509809 on BOTTOM: 3.17,25.96 4.18,24.96 4.18,18.25 1.8,15.88 1.8,11.68 3.84,9.65 7.34,9.65 8,8.99 8,4.7 10.92,1.78 25.6,1.78 27.66,3.84 27.66,4.66 28.27,5.27 28.27,6.96 30.25,6.96 30.3,6.91 30.3,5.11 30.68,4.72 30.68,3.33 31.52,2.49 31.52,0.56 31.06,0.1 0.2,0.1 0.05,0.25 0.05,25.7 0.3,25.96
N11618494 on BOTTOM: 86.56,40.82 86.08,41.3 82.55,41.3 82.14,40.89 80.14,40.89 78.54,39.29 78.54,36.5 79.17,35.86 81.69,35.86 85.33,39.51 86.14,39.51 86.56,39.93
N11648004 on BOTTOM: 59.16,61.06 62.84,61.06 62.92,60.99 62.92,59.59 59.05,59.59 59,59.64 59,60.91
N12700328 on BOTTOM: 64.8,60.86 67.06,60.86 68.45,59.46 68.45,57.78 68.38,57.71 66.98,57.71 66.9,57.78 66.9,58.95 66.24,59.61 64.87,59.61 64.8,59.69
N12700744 on BOTTOM: 64.21,50.27 64.19,50.29 64.19,51.49 64.24,51.54 65.84,51.54 66.12,51.82 66.12,52.98 67.59,52.98 68.38,53.77 69.57,53.77 69.65,53.7 69.65,50.77 69.14,50.27
N12706416 on TOP: 121.06,19.41 122,18.47 122,16.18 121.62,15.8 112.12,15.8 111.51,16.41 111.51,18.95 111.96,19.41
N12706416 on BOTTOM: 109.17,20.98 109.17,22.35 108.99,22.53 107.62,22.53 107.42,22.33 107.42,21.03 109.4,19.05 109.4,17.98 111.81,15.57 121.28,15.57 122.02,16.31 122.02,18.47 120.78,19.71 110.44,19.71
N12706737 on TOP: 102.39,18.59 102.39,16.54 102.03,16.18 100.63,16.18 100.3,16.51 100.3,19.53 102.67,21.89 106.73,21.89 108.29,23.46 122.64,23.46 122.94,23.16 122.94,21.13 122.15,20.35 110.87,20.35 110.21,19.68 105.08,19.68 104.83,19.43 103.23,19.43
N12706737 on BOTTOM: 78.74,14.61 71.37,7.24 71.37,1.91 69.75,0.28 58.88,0.28 58.29,0.86 58.29,6.17 71.08,18.96 101.13,18.96 102.41,17.68 102.41,15.24 101.78,14.61
N12706737 on BOTTOM: 125.2,21.23 124.24,20.28 122.59,20.28 121.97,20.9 112.73,20.9 112.57,20.75 111.25,20.75 110.59,21.41 110.59,23.57 111.96,24.94 124.46,24.94 125.2,24.21
N12714802 on BOTTOM: 88.09,4.31 86.53,4.31 85.98,4.85 83.36,4.85 83.26,4.95 83.26,6.81 88.01,6.81 88.09,6.73
N12720334 on BOTTOM: 81.28,9.88 81.28,4.62 78.05,4.62 76.71,3.28 76.76,3.23 76.76,1.68 75.82,0.74 74.4,0.74 73.79,1.35 73.79,3.23 78.47,7.91 78.47,8.9 79.45,9.88
N12827596 on TOP: 6.96,26.09 13.74,26.09 14.61,25.22 14.61,24.36 13.59,23.34 6.9,23.34 6.9,26.02
N12827596 on BOTTOM: 14.61,25.22 14.61,24.36 13.26,23.01 8.13,23.01 7.65,23.5 7.65,26.09 8.2,26.64 13.18,26.64
N12850742 on BOTTOM: 50.25,47.13 49.34,47.13 49.33,47.12 48.82,47.62 48.82,48.72 49.48,49.38 49.48,56.64 53.75,56.64 56.16,54.23 56.16,52.43 54.81,51.08 54.2,51.08
N12884562 on TOP: 27.03,26.95 29.16,24.82 41.1,24.82 41.55,25.27 41.55,26.75 40.94,27.36 30.68,27.36 30.18,27.86 30.18,31.6 29.62,32.16 27.56,32.16 27.03,31.62
N12884562 on BOTTOM: 22.76,42.52 30.15,35.13 30.15,29.26 29.88,28.99 27.47,28.99 27.15,29.31 27.15,34.09 22.66,38.58 13.13,38.58 12.4,39.32 12.4,41.88 13.03,42.52
N12884633 on TOP: 35.58,22.29 41.52,16.36 41.52,10.35 41.24,10.07 39.51,10.07 38.86,10.72 38.86,16.46 34.95,20.37 34.11,20.37 33.78,20.04 33.78,16.81 33.81,16.79 30.63,13.61 30.61,13.61 30.61,10.97 30.43,10.79 28.3,10.79 27.97,11.13 27.97,15.72 30.68,18.44 30.68,20.35 32.77,22.43 35.44,22.43
N12884633 on BOTTOM: 35.18,22.69 41.52,16.36 41.52,10.48 41.1,10.06 39.9,10.06 38.71,11.25 38.71,16.61 34.65,20.68 34.14,20.68 33.78,20.32 33.78,16.81 33.81,16.79 30.63,13.61 30.61,13.61 30.61,10.54 30.28,10.21 30.28,9.3 30.25,9.27 28.27,9.27 28.27,10.19 27.97,10.49 27.97,15.72 30.86,18.62 30.86,25.43 32.21,26.77 32.21,31.6 32.64,32.03 34.75,32.03 35.18,31.6
N12889668 on BOTTOM: 91.82,44.88 95.63,44.88 96.52,43.99 96.52,42.72 96.42,42.62 92.68,42.62 91.82,43.48
N12891407 on BOTTOM: 69.6,56.46 66.32,56.46 66.24,56.39 66.24,54.76 66.32,54.69 69.47,54.69 69.88,55.09 69.88,56.18
N12908406 on TOP: 12.88,20.73 14.2,20.73 14.63,20.29 14.63,14.71 12.32,12.4 5,12.4 4.37,13.03 4.37,14.61 5.03,15.27 7.42,15.27
N12908406 on BOTTOM: 12.88,20.73 14.2,20.73 14.63,20.29 14.63,14.61 12.42,12.4 5,12.4 4.37,13.03 4.37,14.61 5.03,15.27 7.42,15.27
N12908860 on TOP: 16.48,30.89 20.55,26.82 20.57,26.82 20.57,18.82 23.75,15.65 23.75,11.56 23.25,11.06 21.27,11.06 20.65,11.68 20.65,15.95 17.14,19.46 17.14,26.59 14.54,29.2 13.74,29.2 12.29,30.65 12.29,33.86 12.32,33.86 12.98,34.52 15.85,34.52 16.48,33.88
N12908860 on BOTTOM: 16.66,30.71 20.55,26.82 20.57,26.82 20.57,23.7 19.56,22.68 19.56,19.84 23.75,15.65 23.75,11.18 23.27,10.69 23.27,9.42 23.16,9.32 21.31,9.32 21.26,9.37 21.26,10.52 20.65,11.13 20.65,15.95 17.14,19.46 17.14,26.47 12.29,31.32 12.29,33.58 13.26,34.54 15.42,34.54 16.66,33.3
N12919791 on TOP, BOTTOM: 58.19,41.22 51.97,41.22 51.36,41.83 49.12,41.83 48.82,42.14 48.82,43.59 49.91,44.68 49.94,44.68 54.95,49.7 55.02,49.7 55.77,50.44 59.26,50.44 59.77,49.94 59.77,46.79 59.79,46.76 59.79,42.82
N12926277 on BOTTOM (solid shape): 24.16,22.5 23.65,22.5 23.65,19.3 24.16,19.3 24.16,18.69 21.97,18.69 21.97,23.11 24.16,23.11
N12926277 on BOTTOM: 22.1,25.53 24.03,25.53 24.16,25.4 24.16,22.83 22,22.83 22,25.43
N12926285 on BOTTOM (solid shape): 29.36,18.72 27.18,18.72 27.18,19.33 27.69,19.33 27.69,22.53 27.18,22.53 27.18,23.14 29.36,23.14
N12926285 on BOTTOM: 27.48,25.4 29.24,25.4 29.39,25.25 29.39,23.01 29.29,22.91 27.28,22.91 27.2,22.99 27.2,25.12
N12928762 on TOP: 11.71,7.34 19.96,7.34 20.98,6.32 23.27,6.32 23.57,6.02 23.57,3.61 23.06,3.1 21.44,3.1 19.94,4.6 12.04,4.6 11.15,5.49 11.15,6.78
N12928762 on BOTTOM: 11.71,7.34 19.94,7.34 21.01,6.27 21.11,6.27 21.29,6.45 21.29,6.86 21.44,7.01 23.11,7.01 23.29,6.83 23.29,5.16 23.57,4.88 23.57,3.94 22.89,3.25 21.41,3.25 20.07,4.6 12.04,4.6 11.15,5.49 11.15,6.78
N12942914 on BOTTOM: 110.13,39.47 110.13,35.41 110.03,35.31 108.28,35.31 108.1,35.48 108.1,39.65 108.13,39.67 108.15,39.67 108.38,39.9 109.7,39.9
N12942914 on BOTTOM: 85.29,7.92 83.34,7.92 83.29,7.98 83.29,9.93 83.34,9.98 87.86,9.98 88.09,9.75 88.09,8.43 85.8,8.43
N13029746 on BOTTOM: 82.75,45.62 84.05,45.62 84.05,42.19 84.02,42.16 82.91,42.16 82.75,42.32

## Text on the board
Ref Des/Silkscreen Top: N | L | DER-1019 | REV G | 2618 | S/N | +12V | RTN | +89V
TOLERANCE_BOTTOM: 14.  FAB HOUSE LOGO,DATE CODE TO BE IN SILK SCREEN ONLY.DO NOT USE COPPER. | 13.  MATERIAL FR4 COPPER 2oz THICKNESS 0.062" | PLEASE DELETE THIS PIN
User.8: FIGURE | FINISHED_SIZE | 18.0 | 20.0 | 30.0 | 35.0 | 40.0 | 50.0 | 60.0 | 63.0 | 70.0 | 90.0 | DRILL CHART: TOP to BOTTOM | ALL UNITS ARE IN MILS | TOLERANCE_DRILL | +3.0/-3.0 | +0.0/-0.0 | PLATED | QTY | 3 | 29 | 6 | 10 | 7 | 16 | 4 | 2 | 13
